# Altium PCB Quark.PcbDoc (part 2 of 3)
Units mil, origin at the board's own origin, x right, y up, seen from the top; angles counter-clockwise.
Board outline 1220.47 x 944.88 mil, 6 copper layers (Top1, Signal2, Gnd3, Power4, Signal5, Bottom6), stack 32.534 mil thick; 106 components, 182 nets, 776 pads, 404 vias.
Unrouted connection lines stored in the file: 82.
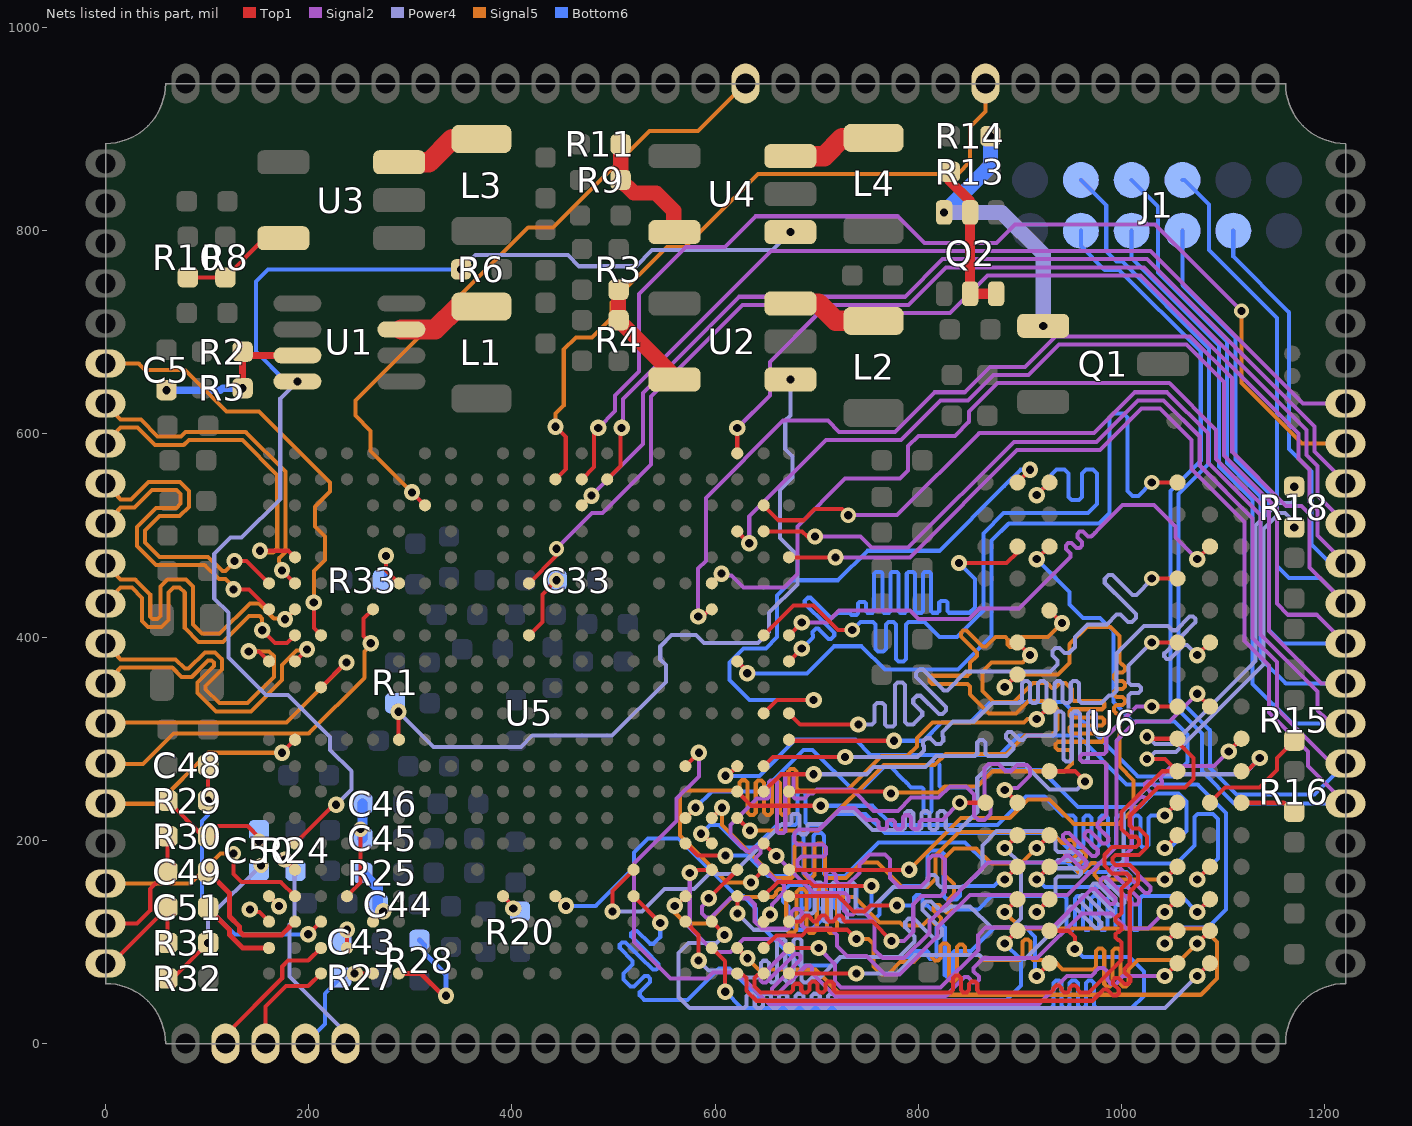
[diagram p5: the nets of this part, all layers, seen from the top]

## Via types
v1: diameter 16, hole 8, Top1 to Bottom6, tented both sides, 238 vias
v2: diameter 15, hole 8, Top1 to Bottom6, tented both sides, 166 vias

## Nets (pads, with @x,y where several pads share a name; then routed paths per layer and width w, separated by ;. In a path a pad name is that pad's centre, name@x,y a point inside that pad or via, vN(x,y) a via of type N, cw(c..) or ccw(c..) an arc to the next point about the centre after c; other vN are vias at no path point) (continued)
GPIOL8/PWR-STB: R6.1 U1.8 U4.1 U5.T2 | length 1265.3
  Top1 w4: U5.T2@186.46,197 224.46,235 v1(227,235)
  Power4 w4: v2(188.82,651.61) 172,634.8 172,536 134,498 123,498 107,482 107,438 121,424 121,380 158,343 179.56,343 221,301.56 221,289 242,268 242,250 v1(227,235) ; v2(350,762) 364,776 455,776 466,765 522,765 538,781 656.46,781 v2(674.06,798.6)
  Bottom6 w4: v2(188.82,651.61) 177.39,651.61 148,681 148,750 160,762 v2(350,762)
GPIOL9/PWR-DRAM: R1.1 U2.1 U5.M6 | length 765.6
  Top1 w4: v1(288.32,326.5) 288.32,299.5 U5.M6@288.82,299
  Power4 w4: v1(288.32,326.5) 322.82,292 409,292 420,303 498.49,303 551.49,356 551.49,372.51 546,378 546,391 557,402 581,402 589,394 642,394 653,405 653,424 681,452 681,480.35 664,497.35 664,545 676,557 676,578 669,585 669,613 674.06,618.06 v2(674.06,653.6)
GPIOL10/PWR-LED: pad.19 U5.V2 | length 227.8
  Top1 w4: v2(126,187) 126,167 134,159 172.46,159 U5.V2@186.46,145
  Signal5 w4: pad.19@0,157.48 83.48,157.48 113,187 v2(126,187)
HCEC: pad.16 U5.G5 | length 366.2
  Top1 w4: v1(261,394) 254,401 254,418.13 U5.G5@263.23,427.36
  Signal5 w4: pad.16@0.59,275 37,275 67,305 200,305 255,360 255,385.66 261,391.66 v1(261,394)
HHPD: pad.17 U5.M2 | length 212.3
  Top1 w4: v1(173.66,286.2) U5.M2@186.46,299
  Signal5 w4: pad.17@0.22,236 51,236 101.2,286.2 v1(173.66,286.2)
HSCL: pad.6 U5.H3 | length 437.2
  Top1 w4: v1(205,434) 205,408.82 U5.H3@212.05,401.77
  Signal5 w4: pad.6@0,669.29 32.71,669.29 ; 33,669 39,663 78,663 119,622 151,622 221,552 221,543.31 206,528.31 206,509 216,499 216,476 205,465 v1(205,434)
HSDA: pad.15 U5.K3 | length 295.8
  Top1 w4: U5.K3@212.05,350.59 236.46,375 v1(237.15,375)
  Signal5 w4: pad.15@1.04,316 178.15,316 v1(237.15,375)
HTX0_N: pad.9 U5.F1 | length 327.8
  Top1 w4: v1(127,475) 138.82,475 U5.F1@160.87,452.95
  Signal5 w4: pad.9@0,551.18 0,550.71 12.54,538.18 12.54,537.84 14.88,535.5 25.18,535.5 42.51,552.83 73.17,552.83 82,544 82,528 73,519 53,519 39,505 39,493 53,479 100.97,479 114.97,465 118.28,465 127,473.72 v1(127,475)
HTX0_P: pad.10 U5.G1 | length 327.4
  Top1 w4: v1(126,447) 141.23,447 U5.G1@160.87,427.36
  Signal5 w4: pad.10@0,511.81 0,512.28 12.54,524.82 12.54,525.15 14.88,527.5 28.5,527.5 45.83,544.83 69.86,544.83 74,540.69 74,531.31 69.69,527 49.69,527 31,508.31 31,489.69 49.69,471 97.66,471 111.66,457 118.28,457 126,449.28 v1(126,447)
HTX1_N: pad.11 U5.G2 | length 326.3
  Top1 w4: v1@173.66,414.57 v1(176.66,417.57) U5.G2@186.46,427.36
  Signal5 w4: pad.11@0,472.44 0,471.64 14.88,456.76 29.24,456.76 44,442 44,420.34 46.34,418 51,418 54,421 54,450 60.76,456.76 79.24,456.76 86,450 86,412.4 95.01,403.39 112.39,403.39 142,433 150.88,433 165.59,418.29 175.93,418.29 v1(176.66,417.57)
HTX1_P: pad.12 U5.H2 | length 328.6
  Top1 w4: v1(154.23,406.77) 167,394 178.69,394 U5.H2@186.46,401.77
  Signal5 w4: pad.12@0,433.07 0,433.88 14.88,448.76 25.93,448.76 36,438.69 36,416 42,410 55,410 62,417 62,444 66.76,448.76 72.93,448.76 78,443.69 78,409.09 91.7,395.39 115.7,395.39 141.09,420.77 151.8,420.77 154.14,418.43 154.14,406.86 v1(154.23,406.77)
HTX2_N: pad.14 U5.J2 | length 328.8
  Top1 w4: U5.J2@186.46,376.18 v1(198.25,387.98) v1@199.25,388.98
  Signal5 w4: pad.14@0,354.33 0,354.8 12.54,367.34 12.54,367.67 14.88,370.02 18.19,370.02 ; 18.21,370 65.69,370 74.78,360.91 84.88,360.91 101.03,377.06 104.5,377.06 106.68,374.87 106.68,371.4 98,362.72 90.54,355.25 90.54,345.15 98,337.69 108.69,327 143,327 173.63,357.63 173.63,372.63 187.9,386.9 197.18,386.9 v1(198.25,387.98)
HTX2_P: pad.13 U5.J1 | length 325.7
  Top1 w4: v1(141,386) 151.05,386 U5.J1@160.87,376.18
  Signal5 w4: pad.13@0,393.7 0,393.23 12.54,380.7 12.54,380.36 14.88,378.02 68.98,378.02 78.09,368.91 81.57,368.91 97.71,385.06 107.82,385.06 114.68,378.19 114.68,368.09 98.54,351.94 98.54,348.46 112,335 139.69,335 165.63,360.94 165.63,381.37 161.03,385.97 v1(141,386)
HTXC_N: pad.8 U5.E2 | length 328.3
  Top1 w4: v1(152,485) 180,485 U5.E2@186.46,478.54
  Signal5 w4: pad.8@0,590.55 0,591.36 14.88,606.24 31.45,606.24 48.69,589 77,589 82,594 134.69,594 169,559.69 169,487.2 165.09,483.29 153.71,483.29 v1(152,485)
HTXC_P: pad.7 U5.F2 | length 327.9
  Top1 w4: v1(173.66,465.75) U5.F2@186.46,452.95
  Signal5 w4: pad.7@0,629.92 0,629.12 14.88,614.24 34.76,614.24 51.34,597.66 74.34,597.66 78.69,602 138,602 177,563 177,483.89 173.09,479.98 170.75,477.64 170.75,474.32 171.36,473.71 171.36,468.04 v1(173.66,465.75)
I2C0_SCL: pad.61 U5.F11 | length 1115.7
  Top1 w4: U5.F11@416.77,452.95 444,480.18 v2(444,487) v2@444,491
  Signal2 w4: v2(444,487) 479,522 489,522 537,570 537,637 627,727 790.31,727 827.31,764 1021.94,764 1182,603.94 1182,579.31 1193,568.31 1193,539.28 pad.61@1220.47,511.81
I2C0_SDA: pad.62 U5.C13 | length 992.3
  Top1 w4: U5.C13@468.77,529.72 v1(478.27,539.22) v1@481.27,542.22
  Signal2 w4: v1(478.27,539.22) 529,589.95 529,640.31 623.69,735 787,735 824,772 1025.25,772 1190,607.25 1190,582.63 1220.47,552.15 pad.62@1220.47,551.18
I2C1_SCL: pad.63 U5.B13 | length 1082.4
  Top1 w4: U5.B13@468.77,555.32 481,567.54 481,601 v1@486,606
  Signal2 w4: v1(485,606) 501.4,622.4 501.4,637.71 525,661.31 525,737.69 571.31,784 609.63,784 639.85,814.22 779.78,814.22 806,788 877,788 895,806 1033,806 v2(1118,721)
  Signal5 w4: v2(1118,721) 1118,650 1177.45,590.55 pad.63@1220.47,590.55
I2C1_SDA: pad.64 U5.B14 | length 919.1
  Top1 w4: U5.B14@493.77,555.32 507,568.54 507,605 v1(508,606)
  Signal2 w4: v1(508,606) 509.4,607.4 509.4,634.4 655,780 1028.57,780 1178.65,629.92 pad.64@1220.47,629.92
I2C2_SCL: pad.78 U5.B12 | length 708.1
  Top1 w4: U5.B12@442.77,555.32 453,565.54 453,597 v1(443,607)
  Signal5 w4: v1(443,607) 443,620 451,628 451,683 463,695 479,695 498,714 498,729.31 552.69,784 570.37,784 606.37,820 640.87,854.5 642.37,856 721.15,856 745.63,856 768.31,856 839,856 851,868 851,902 866.14,917.14 pad.78@866.14,944.88
I2C2_SDA: pad.84 U5.C7 | length 644.7
  Top1 w4: v1(301.61,542.52) U5.C7@314.41,529.72
  Signal5 w4: v1(301.61,542.52) 261,583.13 261,603 246,618 246,632.94 416.06,803 440.25,803 535.25,898 583.04,898 pad.84@629.92,944.88
IR-RX: pad.26 R24.1 U5.U2 | length 216.9
  Top1 w4: v1@173.96,183.5 v1(176.36,181.1) U5.U2@186.46,171
  Power4 w4: v1(176.36,181.1) 186,171.46 186,122 181,117 181,66 pad.26@236.22,10.78
KEYADC: pad.25 R27.2 U5.AA5 | length 97.6
  Top1 w4: v1(245.23,69) U5.AA5@263.23,69
  Bottom6 w4: pad.25@196.85,0 216,19.15 216,49 R27.2@232,65
LINEINL: U5.V1 | length 18.1
  Top1 w4: U5.V1@160.87,145 v1@173.66,132.2
  other v1: 170.66,135.2
LINEINR: U5.W1 | length 23.7
  Top1 w4: v1(142.07,131.8) 144.37,129.5 151.37,129.5 U5.W1@160.87,120
LINEOUTL: pad.24 U5.AA3 | length 104.5
  Top1 w4: pad.24@157.48,0 157.48,36.48 177.5,56.5 199.55,56.5 U5.AA3@212.05,69
LINEOUTR: pad.23 U5.Y3 | length 143.2
  Top1 w4: pad.23@118.11,1.42 118.11,8.42 173.96,64.27 173.96,75.96 179.5,81.5 199.55,81.5 U5.Y3@212.05,94
MBIAS: C48.1 R29.2 U5.W3 | length 272.2
  Top1 w4: v2(101,239) C48.1@101,274 ; v1(199.55,107.5) U5.W3@212.05,120
  Bottom6 w4: v2(101,239) 101,225 95,219 95,140 127.5,107.5 v1(199.55,107.5)
MIC1N: C51.2 pad.21 R31.2 | length 118.9
  Top1 w4: pad.21@0,78.74 5.74,78.74 C51.2@61,134 R31.2@61,99
MIC1P: C49.2 pad.20 R30.1 | length 129.3
  Top1 w4: pad.20@0,118.11 31,118.11 44,131.11 44,152 C49.2@61,169 R30.1@61,204
MICIN1N: C51.1 U5.Y1 | length 79.9
  Top1 w5: C51.1@101,134 101,133 122,112 122,107 135,94 U5.Y1@160.87,94
MICIN1P: C49.1 U5.W2 | length 132.8
  Top1 w5: C49.1@101,169 122,148 122,125 132,115 132,110.27 135.27,107 173.46,107 U5.W2@186.46,120
NetC5_1: C5.1 R2.1 R5.2 U1.7 | length 161.9
  Top1 w7: v2(135,645) R2.1@135,681 ; R2.1@138.8,677.2 U1.7@188.82,677.2
  Bottom6 w7: v2(60,643) 113,643 115,645 v2(135,645)
NetC33_1: C33.1 U5.H11 | length 65.5
  Top1 w4: U5.H11@416.77,401.77 430,415 430,442 v2(444,456)
NetC43_1: C43.1 U5.Y4 | length 18
  Top1 w4: U5.Y4@237.64,94 v1(237.64,112)
NetC44_2: C44.2 R25.2 U5.W5 | length 57.9
  Top1 w4: U5.W5@263.23,120 v1(273.33,130.1) v1@275.73,132.5
  Bottom6 w10: R25.2@253,168 268,153 C44.2@268,134
NetC45_2: C45.2 C46.2 U5.V4 | length 105.5
  Top1 w4: U5.V4@237.64,145 251,158.36 v2(251,211)
  Bottom6 w10: C45.2@253,202 C46.2@253,236
NetC50_1: C50.1 R31.1 R32.2 | length 152.4
  Top1 w4: R32.2@61,64 66,64 v2(101,99)
  Power4 w4: v2(101,99) 101,123.32 v2(153,175.31)
NetC50_2: C50.2 R29.1 R30.2 | length 113.2
  Top1 w4: R29.1@61,239 96,204 R30.2@101,204 101.34,204 111.34,214 140,214 v2@151,203
  other v2: 151,199
NetL1_1: L1.1 U1.3 | length 88.1
  Top1 w20: U1.3@291.18,702.8 324.49,702.8 346.97,725.28 L1.1@370,725.28
NetL2_1: L2.1 U2.3 | length 89
  Top1 w20: U2.3@674.06,728.4 701.6,728.4 718.72,711.28 L2.1@756,711.28
NetL3_1: L3.1 U3.3 | length 90.4
  Top1 w20: U3.3@289.06,867.4 318.4,867.4 341.28,890.28 L3.1@370,890.28
NetL4_1: L4.1 U4.3 | length 89.3
  Top1 w20: U4.3@674.06,873.4 707.4,873.4 725.28,891.28 L4.1@756,891.28
NetQ1_1: Q1.1 Q2.3 R14.1 | length 279
  Power4 w15: v2(825.41,818) 882,818 922.94,777.06 v2(922.94,706.4)
  Bottom6 w15: v2(825.41,818) 871,863.59 v2(871,893)
NetQ2_2: Q2.2 Q2.5 Q2.6 R13.2 | length 153.9
  Top1 w10: R13.2@831,858 831,849 851,829 Q2.2@851,818 Q2.5@851,738 Q2.6@876.59,738
NetR3_2: R3.2 R4.2 U2.5 | length 111.2
  Top1 w10: U2.5@560.06,653.6 U2.5@560.06,656.94
  Top1 w15: R3.2@505,742 R4.2@505,712 U2.5@560.06,656.94
NetR8_2: R8.2 R10.2 U3.5 | length 110
  Top1 w4: R10.2@81,754 R8.2@118,754 156.6,792.6 U3.5@175.06,792.6
NetR9_1: R9.1 R11.2 U4.5 | length 121.8
  Top1 w10: U4.5@559.19,798.6 U4.5@560.06,798.6
  Top1 w15: R11.2@507,885 R9.1@507,850 520,837 542,837 559.19,819.81 U4.5@559.19,798.6
NetR15_1: R15.1 U6.L8 | length 115.3
  Top1 w4: U6.L8@1087,237 1102,252 1136,252 1153,269 1153,281 R15.1@1170,298
NetR16_1: R16.1 U6.L9 | length 55.7
  Top1 w4: U6.L9@1118,237 1159.66,237 1168.66,228 R16.1@1170,228
NetR20_1: R20.1 U5.V10 | length 17.7
  Top1 w4: U5.V10@391.18,145 v1@403.68,132.5
  other v1: 401.28,132.9
NetR28_2: R28.2 U5.AA6 | length 121.1
  Top1 w5: U5.AA6@288.82,69 310.38,69 332.38,47 v1(335,47)
  Bottom6 w5: R28.2@309,102 313.84,97.16 313.84,89.16 335,68 v1(335,47)
NetR33_2: R33.2 U5.F6 | length 65.6
  Top1 w4: v1@276,484 276,465.77 U5.F6@288.82,452.95
  Bottom6 w4: R33.2@273,456 276,459 v1@276,484
  other v1: 276,480
SA0: U5.T17 U6.N3 | length 757
  Top1 w4: U5.T17@570.77,197 582.89,184.89 v1(610.11,184.89) ; v1(916.51,161.5) U6.N3@929.01,174
  Bottom6 w4: v1(610.11,184.89) 632.11,184.89 652,165 674.5,165 677,167.5 677,204.5 679.5,207 684.5,207 687,204.5 687,167.5 689.5,165 694.5,165 697,167.5 697,204.5 699.5,207 704.5,207 707,204.5 707,167.5 709.5,165 728,165 761,198 846,198 866,178 947,178 956,169 1005,169 1009,165 1009,158 1005,154 924.85,154 917.35,161.5 v1(916.51,161.5)
SA1: U5.U18 U6.P7 | length 831.6
  Top1 w4: v1(575,168) 577.3,170.3 582.64,170.3 583.34,171 U5.U18@596.77,171 ; v1(1042.5,129.5) U6.P7@1055,142
  Signal2 w4: v1(575,168) 575,114 599,90 615,90 628,103 662,103 670.29,94.71 670.29,91.32 644.6,65.63 644.6,62.23 646.86,59.97 650.25,59.97 677.64,87.36 678.53,88.25 681.92,88.25 684.19,85.98 684.19,82.59 655.91,54.31 655.91,50.92 658.17,48.66 661.57,48.66 688.96,76.04 689.84,76.93 693.24,76.93 695.5,74.67 695.5,71.28 695.5,69.5 718,47 827,47 837.5,57.5 841.36,61.36 845.32,65.32 848.71,65.32 853.87,60.16 857.26,60.16 859.52,62.42 859.52,65.82 854.37,70.97 854.37,74.37 855.5,75.5 864,84 917,84 961,128 989.97,128 1004.97,113 1026,113 v1(1042.5,129.5)
SA2: U5.V19 U6.P3 | length 793.4
  Top1 w4: U5.V19@621.77,145 622,144.77 v1(622,128) ; v1(916.51,129.5) U6.P3@929.01,142
  Power4 w4: v1(622,128) 638,112 670,112 677.5,119.5 680.33,122.33 685.99,127.99 ; 686,128 690,128 695.6,128 698,130.4 698,156.18 700.4,158.58 703.6,158.58 706,156.18 706,128 706,122.6 708.4,120.2 711.6,120.2 714,122.6 714,128 714,156.18 716.4,158.58 719.6,158.58 722,156.18 722,128 722,122.6 724.4,120.2 727.6,120.2 730,122.6 730,128 730,156.18 732.4,158.58 735.6,158.58 738,156.18 738,130.4 740.4,128 746,128 749,128 750.5,129.5 775,154 804,154 806,154 809,157 809,163 812,166 816,166 819,163 819,157 822,154 828,154 845,154 863,172 863,195 877,209 926,209 935,200 935,192.5 935,190.9 937.4,188.5 957.6,188.5 960,186.1 960,182.9 957.6,180.5 937.4,180.5 935,178.1 935,174.9 937.4,172.5 957.6,172.5 960,170.1 960,166.9 957.6,164.5 937.4,164.5 935,162.1 935,161 935,147.99 v1(916.51,129.5)
SA3: U5.V20 U6.N2 | length 758.1
  Top1 w4: U5.V20@647.77,145 661.77,159 693,159 697,155 v1(754,155) v1@750,159 ; v1(885.01,161.5) U6.N2@897.51,174
  Bottom6 w4: v1(754,155) 754,137 749,132 741,132 739,134 739,153 736,156 735,156 733,156 726.6,156 725,154.4 725,134.6 723.4,133 718.6,133 717,134.6 717,154.4 715.4,156 710.6,156 709,154.4 709,134.6 707.4,133 702.6,133 701,134.6 701,154.4 699.4,156 694.6,156 693,154.4 693,134.6 691.4,133 686.6,133 685,134.6 685,154.4 683.4,156 677,156 673,156 667,150 667,140 672,135 672,120 680,112 695,112 704,121 756,121 762,127 762,140 777,155 801,155 ; 803.4,155 801,155 ; v1(885.01,161.5) 881.01,161.5 874.51,155 856,155 844.2,155 841,151.8 841,145.2 837.8,142 828.2,142 825,145.2 825,155 825,186.8 821.8,190 812.2,190 809,186.8 809,158.2 805.8,155 801,155
SA4: U5.V21 U6.P8 | length 757.8
  Top1 w4: U5.V21@672.77,145 721,145 736,130 747,130 753,136 v1(779,136) ; v1(1074.5,129.5) U6.P8@1087,142
  Bottom6 w4: v1(779,136) 792,136 793.6,136 796,138.4 796,143.6 798.4,146 801.6,146 804,143.6 804,138.4 806.4,136 809,136 813,132 859,132 872,145 934,145 938,145 943.6,145 946,142.6 946,114.4 948.4,112 951.6,112 954,114.4 954,142.6 956.4,145 959.6,145 962,142.6 962,114.4 964.4,112 967.6,112 970,114.4 970,142.6 972.4,145 975.6,145 978,142.6 978,114.4 980.4,112 983.6,112 986,114.4 986,142.6 988.4,145 991.6,145 994,142.6 994,114.4 996.4,112 999.6,112 1002,114.4 1002,142.6 1004.4,145 1007.6,145 1010,142.6 1010,114.4 1012.4,112 1015.6,112 1018,114.4 1018,142.6 1020.4,145 1023,145 1059,145 v1(1074.5,129.5)
SA5: U5.Y19 U6.P2 | length 776.2
  Top1 w4: U5.Y19@621.77,94 v1(631.87,83.9) v1@634.27,81.5 ; v1(885.01,129.5) U6.P2@897.51,142
  Signal5 w4: v1(631.87,83.9) 642.77,73 698.63,73 723.63,48 1078,48 1094,64 1094,100 1081,113 901.51,113 v1(885.01,129.5)
SA6: U5.Y20 U6.R8 | length 776.2
  Top1 w4: U5.Y20@647.77,94 660.27,106.5 685.5,106.5 691,112 730,112 v1(739,103) ; v1(1074.5,98.5) U6.R8@1087,111
  Signal5 w4: v1@739,98 v1(739,103) 751,103 756,98 756,76 764,68 770,68 782.5,80.5 795.5,80.5 802,87 811.6,87 814,84.6 814,84.28 816.4,81.88 819.6,81.88 822,84.28 822,95.83 824.4,98.23 827.6,98.23 830,95.83 830,63.82 832.4,61.42 835.6,61.42 838,63.82 838,95.1 840.4,97.5 843.6,97.5 846,95.1 846,89.4 848.4,87 859,87 864,82 900.1,82 902.5,84.4 902.5,100.18 904.9,102.58 908.1,102.58 910.5,100.18 910.5,84.4 912.9,82 933,82 942,73 972.6,73 975,75.4 975,91.18 977.4,93.58 980.6,93.58 983,91.18 983,58.4 985.4,56 988.6,56 991,58.4 991,91.18 993.4,93.58 996.6,93.58 999,91.18 999,58.4 1001.4,56 1004.6,56 1007,58.4 1007,73 1016,82 1058,82 v1(1074.5,98.5)
SA7: U5.V15 U6.R2 | length 756.9
  Top1 w4: U5.V15@519.77,145 v1@546,118.77 ; v1(885.01,98.5) U6.R2@897.51,111
  Bottom6 w4: v1(546,118.76) 546,105 543.17,102.17 539.21,98.21 535.82,98.21 523.13,110.9 519.73,110.9 517.47,108.64 517.47,105.25 531.86,90.86 544.3,78.41 544.3,75.02 542.04,72.76 538.65,72.76 526.2,85.2 511.81,99.59 508.42,99.59 506.16,97.33 506.16,93.93 518.85,81.24 518.85,77.85 514.89,73.89 510,69 510,63 512.83,60.17 516.79,56.21 520.18,56.21 530.38,66.41 533.78,66.41 536.04,64.15 536.04,60.75 525.84,50.56 525.84,47.16 529.8,43.2 530,43 534,43 537,43 573,43 604,74 614,74 636.15,51.85 638.41,49.58 645,43 887,43 901,57 901,82.51 v1(885.01,98.5)
SA8: U5.W18 U6.T8 | length 794
  Top1 w4: U5.W18@596.77,120 609.27,107.5 v1(609.27,106.96) ; v1(1074.5,66.5) U6.T8@1087,79
  Power4 w4: v1(609.27,106.96) 601.32,99 574,99 564,89 564,46 575,35 627,35 628.6,35 631,37.4 631,46.6 633.4,49 636.6,49 639,46.6 639,37.4 641.4,35 644.6,35 647,37.4 647,46.6 649.4,49 652.6,49 655,46.6 655,37.4 657.4,35 660.6,35 663,37.4 663,46.6 665.4,49 668.6,49 671,46.6 671,37.4 673.4,35 676.6,35 679,37.4 679,46.6 681.4,49 684.6,49 687,46.6 687,37.4 689.4,35 692.6,35 695,37.4 695,46.6 697.4,49 700.6,49 703,46.6 703,37.4 705.4,35 708.6,35 711,37.4 711,46.6 713.4,49 716.6,49 719,46.6 719,37.4 721.4,35 723,35 1043,35 v1(1074.5,66.5)
SA9: U5.Y18 U6.R3 | length 757.8
  Top1 w4: U5.Y18@596.77,94 609.77,81 609.77,51.23 v1(610,51) ; U6.R3@929.01,111 948,111 954,105 v1(954,93)
  Bottom6 w4: v1(610,51) 626,35 929,35 930.6,35 933,37.4 933,59.6 935.4,62 938.6,62 941,59.6 941,37.4 943.4,35 946.6,35 949,37.4 949,59.6 951.4,62 954.6,62 957,59.6 957,37.4 959.4,35 962.6,35 965,37.4 965,59.6 967.4,62 970.6,62 973,59.6 973,37.4 975.4,35 981,35 982,35 1010,35 1022,47 1022,71 1008,85 962,85 v1(954,93)
SA10: U5.P19 U6.L7 | length 757.4
  Top1 w4: U5.P19@621.77,248 635.77,234 v1(704,234) ; v1(1042.5,224.5) U6.L7@1055,237
  Bottom6 w4: v1(704,234) 755,234 774,215 878,215 906,243 924,243 942.5,224.5 946.5,224.5 952.1,224.5 954.5,222.1 954.5,195.81 956.9,193.41 960.1,193.41 962.5,195.81 962.5,222.1 964.9,224.5 968.1,224.5 970.5,222.1 970.5,195.4 972.9,193 976.1,193 978.5,195.4 978.5,222.1 980.9,224.5 984.1,224.5 986.5,222.1 986.5,195.4 988.9,193 992.1,193 994.5,195.4 994.5,222.1 996.9,224.5 1000.1,224.5 1002.5,222.1 1002.5,195.4 1004.9,193 1008.1,193 1010.5,195.4 1010.5,222.1 1012.9,224.5 1016.1,224.5 1018.5,222.1 1018.5,195.4 1020.9,193 1024.1,193 1026.5,195.4 1026.5,222.1 1028.9,224.5 1030,224.5 v1(1042.5,224.5)
SA11: U5.N19 U6.R7 | length 757.7
  Top1 w4: v1@609.27,260.5 U5.N19@621.77,273 ; v1(1042.5,98.5) U6.R7@1055,111
  Bottom6 w4: v1(610.27,263.5) 643.5,263.5 679,299 738,299 753,284 880,284 899,303 957,303 1005,255 1075,255 1103,227 1103,132 1085,114 1058,114 v1(1042.5,98.5)
SA12: U5.R18 U6.N7 | length 775.9
  Top1 w4: U5.R18@596.77,222 v1(606.87,232.1) v1@609.27,234.5 ; v1(1042.5,161.5) U6.N7@1055,174
  Signal5 w4: v1(606.87,232.1) 606.87,215.13 659,163 673,163 675,163 678,166 678,194 681,197 685,197 688,194 688,166 691,163 695,163 698,166 698,194 701,197 705,197 708,194 708,166 711,163 729,163 744,178 760,178 784,154 809,154 817,162 817,185 840,208 931,208 941.63,197.37 945.03,197.37 948,200.34 951.39,200.34 953.65,198.08 953.65,194.68 948.99,190.01 944.32,185.35 944.32,181.95 946.58,179.69 949.98,179.69 954.64,184.36 959.31,189.02 962.7,189.02 964.97,186.76 964.97,183.37 960.3,178.7 955.63,174.03 955.63,170.64 957.89,168.38 961.29,168.38 965.96,173.04 970.62,177.71 974.02,177.71 976.28,175.45 976.28,172.05 973.31,169.08 973.31,165.69 977.5,161.5 v1(1042.5,161.5)
SA13: U5.V12 U6.T3 | length 758.1
  Top1 w4: U5.V12@442.77,145 v1@455.27,132.5 ; v1(916.51,66.5) U6.T3@929.01,79
  Bottom6 w4: v1(453.27,135.5) 482.5,135.5 520,173 520,188 534,202 564,202 621,145 628,145 640,133 640,121 684,77 716,77 724,85 792,85 798,91 802,91 808.4,91 810,89.4 810,85 811.6,83.4 816.4,83.4 818,85 818,91 818,114.4 819.6,116 824.4,116 826,114.4 826,91 826,67.6 827.6,66 832.4,66 834,67.6 834,89.4 835.6,91 841,91 852,91 875,114 906,114 915,105 915,68.01 v1(916.51,66.5)
SA14: U5.N17 U6.T7 | length 831.6
  Top1 w4: U5.N17@570.77,273 v1(584,286.23) ; v1(1042.5,66.5) U6.T7@1055,79
  Signal2 w4: v1(584,286.23) 584,263 562,241 562,219 520,177 520,100 556,64 592,64 598,70 622,70 653,39 919,39 946.5,66.5 968,66.5 970.4,66.5 974,70.1 974,70.65 977.6,74.25 982.4,74.25 986,70.65 986,66.5 986,62.35 989.6,58.75 994.4,58.75 998,62.35 998,62.9 1001.6,66.5 1007,66.5 v1(1042.5,66.5)
SA15: U5.R17 U6.M7 | length 756.8
  Top1 w4: U5.R17@570.77,222 v1(580.87,232.1) v1@583.27,234.5 ; v1(1042.5,192.5) U6.M7@1055,205
  Bottom6 w4: v1(580.87,232.1) 596.77,248 646,248 687,289 696,289 736,249 743,249 766,272 773,272 785,260 787.83,257.17 793,252 797,252 803.4,252 805,250.4 805,228.6 806.6,227 811.4,227 813,228.6 813,252 813,274.4 814.6,276 819.4,276 821,274.4 821,253.6 822.6,252 828,252 856,252 873,269 921,269 957,233 1018,233 1031,246 1056,246 1064,238 1064,209 1047.5,192.5 v1(1042.5,192.5)
SBA0: U5.W17 U6.M2 | length 794
  Top1 w4: U5.W17@570.77,120 583.77,107 v1(583.77,81.54) ; v1(885.01,192.5) U6.M2@897.51,205
  Power4 w4: v1(583.77,81.54) 593.32,72 616,72 623,65 642.6,65 645,67.4 645,79.04 647.4,81.44 650.6,81.44 653,79.04 653,62.4 655.4,60 658.6,60 661,62.4 661,101.6 663.4,104 666.6,104 669,101.6 669,62.4 671.4,60 674.6,60 677,62.4 677,101.6 679.4,104 682.6,104 685,101.6 685,62.4 687.4,60 690.6,60 693,62.4 693,62.6 695.4,65 703,65 723,85 781,85 794.5,98.5 796.2,100.2 796.2,105.29 787.15,114.34 787.15,119.43 790.54,122.82 795.63,122.82 807.23,111.23 814.77,103.69 819.86,103.69 823.25,107.08 823.25,112.17 815.71,119.71 804.12,131.31 804.12,136.4 807.51,139.79 812.6,139.79 821.65,130.74 826.74,130.74 828.5,132.5 831,135 851,135 872,114 892,114 901,123 901,176.51 v1(885.01,192.5)
SBA1: U5.T18 U6.N8 | length 757.8
  Top1 w4: v1@584.27,209.5 U5.T18@596.77,197 ; v1(1074.5,161.5) U6.N8@1087,174
  Bottom6 w4: v1(586.27,206.5) 594.77,215 604,215 626,193 639,193 661,215 676,215 678.6,215 681,217.4 681,245.6 683.4,248 686.6,248 689,245.6 689,217.4 691.4,215 697,215 701,215 707,215 718,226 748,226 767,207 932,207 962,177 1054,177 1072,195 1072,223 1075,226 1090,226 1095,221 1095,182 v1(1074.5,161.5)
SBA2: U5.V17 U6.M3 | length 776
  Top1 w4: v1@558.27,132.5 U5.V17@570.77,145 ; v1(916.51,192.5) U6.M3@929.01,205
  Signal5 w4: v1(560.27,135.5) 560.27,128.73 571,118 591,118 617,144 655,144 657,144 660,147 660,149 663,152 667,152 670,149 670,144 670,112 673,109 677,109 680,112 680,144 680,149 683,152 687,152 690,149 690,144 690,112 693,109 697,109 700,112 700,144 700,149 703,152 707,152 710,149 710,144 710,112 713,109 717,109 720,112 720,141 723,144 727,144 737,144 762,119 782,119 785,116 804,116 809.5,121.5 812.9,121.5 816.58,117.83 819.97,117.83 822.23,120.09 822.23,123.48 816.86,128.86 814.97,130.75 814.97,134.14 817.23,136.4 820.63,136.4 822.51,134.51 827.89,129.14 831.28,129.14 833.55,131.4 833.55,134.8 829.87,138.47 829.87,141.87 835,147 835,157 825,167 825,181.69 835.31,192 857,192 872,177 901.01,177 v1(916.51,192.5)
SCAS: U5.U15 U6.K3 | length 794.4
  Top1 w4: v1(499,130) 499,150.23 U5.U15@519.77,171 ; U6.K3@929.01,268 954,268 v1(964,258)
  Power4 w4: v1(499,130) 528,130 550,152 579,152 594,167 617,167 666,216 673.4,216 675,217.6 675,224.4 676.6,226 681.4,226 683,224.4 683,207.6 684.6,206 689.4,206 691,207.6 691,214.4 692.6,216 708,216 721,229 736,229 755,210 783,210 784.6,210 787,212.4 787,226.62 789.4,229.02 792.6,229.02 795,226.62 795,212.4 797.4,210 800.6,210 803,212.4 803,226.62 805.4,229.02 808.6,229.02 811,226.62 811,212.4 813.4,210 816.6,210 819,212.4 819,226.62 821.4,229.02 824.6,229.02 827,226.62 827,212.4 829.4,210 830,210 840,210 858,228 858,261.31 871.69,275 904,275 929,250 956,250 v1(964,258)
SCK_N: R18.1 U5.AA20 U6.K7 | length 1161.3
  Top1 w4: U5.AA20@647.77,69 646.24,67.47 641.9,67.47 638.77,64.34 638.77,56.23 644.9,50.1 674.37,50.1 676.77,52.5 676.77,56.45 679.17,58.85 682.37,58.85 684.77,56.45 684.77,52.5 687.17,50.1 690.37,50.1 692.77,52.5 692.77,58.6 695.17,61 698.37,61 700.77,58.6 700.77,52.5 703.17,50.1 706.37,50.1 708.77,52.5 708.77,58.6 711.17,61 714.37,61 716.77,58.6 716.77,52.5 719.17,50.1 831.6,50.1 834,52.5 834,64.66 836.4,67.06 839.6,67.06 842,64.66 842,52.5 844.4,50.1 847.6,50.1 850,52.5 850,58.78 852.4,61.18 855.6,61.18 858,58.78 858,52.5 860.4,50.1 930.6,50.1 933,52.5 933,54.78 935.4,57.18 938.6,57.18 941,54.78 941,52.5 943.4,50.1 946.6,50.1 949,52.5 949,54.78 951.4,57.18 954.6,57.18 957,54.78 957,52.5 959.4,50.1 968.1,50.1 1000.1,82.1 1000.1,99.6 997.7,102 996.5,102 994.1,104.4 994.1,107.6 996.5,110 997.7,110 1000.1,112.4 1000.1,115.6 997.7,118 996.5,118 994.1,120.4 994.1,123.6 996.5,126 997.7,126 1000.1,128.4 1000.1,152.45 1008.24,160.59 1008.24,164.48 1005.18,167.54 990.84,167.54 983.1,175.28 983.1,185.79 990.84,193.54 1014.04,193.54 1017.1,196.59 1017.1,200.48 1014.04,203.54 1007.84,203.54 1000.1,211.28 1000.1,227.81 ; 1000,227.81 1040.19,268 U6.K7@1055,268 1043,280 v2(1025,280) v2@1025.25,279.75
  Signal2 w4: v2(1025,280) v2@1025.84,280
  Power4 w4: v2(1025,280) 1025.84,280 1032.84,287 1053.77,287 1139.89,373.12 1139.89,506.62 1155.27,522 1161,522 1170,513 v2(1170,508)
SCK_P: R18.2 U5.AA19 U6.J7 | length 1160.9
  Top1 w4: U5.AA19@621.77,69 623.3,67.47 627.65,67.47 630.77,64.34 630.77,51.91 640.59,42.1 971.41,42.1 982.45,53.13 985.84,53.13 991.64,47.33 995.03,47.33 997.29,49.6 997.29,52.99 991.5,58.79 991.5,62.18 993.76,64.45 997.15,64.45 1002.95,58.65 1006.35,58.65 1008.61,60.91 1008.61,64.3 1002.81,70.1 1002.81,73.5 1008.1,78.79 1008.1,149.14 1016.24,157.28 1016.24,167.79 1008.5,175.54 994.16,175.54 991.1,178.59 991.1,182.48 994.16,185.54 1017.36,185.54 1025.1,193.28 1025.1,203.79 1017.36,211.54 1011.16,211.54 1008.1,214.59 1008.1,224.1 1036.1,252.1 1062.4,252.1 1070.8,260.5 1070.8,281.2 1055,297 U6.J7@1055,300 1027,300 v2(1025,302)
  Signal2 w4: v2(1025,302) v2@1025.84,302
  Power4 w4: v2(1025,302) 1025.84,302 1032.84,295 1050.46,295 1131.89,376.43 1131.89,509.94 1153.95,532 1167.66,532 1170,534.34 v2(1170,548)
SCKE0: U5.AA21 U6.K9 | length 795.2
  Top1 w4: U5.AA21@672.77,69 v1(739,69) ; U6.K9@1118,268 1123.5,268 1136,280.5 v1(1136,281)
  Power4 w4: v1(739,69) 779,69 797,87 860,87 864,83 905,83 946.5,124.5 947.63,125.63 947.63,129.03 947.62,132.43 949.88,134.7 953.27,134.7 954.99,132.98 974.37,113.6 977.77,113.6 980.03,115.86 980.03,119.25 960.64,138.64 958.93,140.35 958.93,143.75 961.19,146.01 964.59,146.01 966.3,144.3 985.69,124.91 989.08,124.91 991.34,127.17 991.34,130.57 971.96,149.96 970.24,151.67 970.24,155.06 972.51,157.32 975.9,157.32 977.61,155.61 997,136.22 1000.4,136.22 1002.66,138.49 1002.66,141.88 984.97,159.57 984.97,162.97 986,164 1002,180 1002,229 1038,265 1120.5,265 1136,280.5 v1(1136,281)
SCKE1: U5.Y21 U6.J9 | length 832.2
  Top1 w4: U5.Y21@672.77,94 v1(702,94) ; v1(1105.5,287.5) U6.J9@1118,300
  Signal2 w4: v1(702,94) 718,78 718,61 724,55 822,55 859,92 859,107 866,114 932.31,114 970.45,152.13 973.84,152.13 988.47,137.5 991.87,137.5 994.13,139.76 994.13,143.16 979.5,157.79 979.5,161.18 981.76,163.44 985.15,163.45 1011.69,136.91 1015.08,136.91 1017.34,139.17 1017.34,142.57 993.81,166.1 990.81,169.1 990.81,172.5 993.07,174.76 996.47,174.76 1023,148.22 1026.4,148.22 1028.66,150.49 1028.66,153.88 1005.12,177.42 1005.12,186.81 1010,191.69 1010,234 1018.5,242.5 ; 1018.5,242.5 1021.9,242.5 1022.76,241.64 1026.16,241.64 1028.42,243.9 1028.42,247.3 1025.86,249.86 1023.3,252.42 1023.3,255.81 1025.56,258.08 1028.95,258.08 1031.51,255.51 1034.08,252.95 1037.47,252.95 1039.73,255.22 1039.73,258.61 1038.87,259.47 1038.87,262.87 1040,264 1049,273 1091,273 v1(1105.5,287.5)
SCS0: U5.W20 U6.L2 | length 760.7
  Top1 w4: U5.W20@647.77,120 647.77,120.39 654,126.61 v1(654,127) ; v1(885.01,249.5) U6.L2@897.51,237
  Signal2 w4: v1@655.9,128.9 655.9,136.9 668,149 668,156 664,160 660,160 641,179 640.18,179.82 640.18,183.21 644.63,187.66 644.63,191.05 642.37,193.32 638.97,193.32 634.53,188.87 631.13,188.87 630,190 615,205 615,215 641,241 651.4,241 653,242.6 653,257.4 654.6,259 659.4,259 661,257.4 661,208.6 662.6,207 667.4,207 669,208.6 669,263.69 670.6,265.29 675.4,265.29 677,263.69 677,242.6 678.6,241 688,241 693,246 696.2,246 700.2,250 735,250 756,229 780,229 793,242 820,242 831,253 847,253 855,245 855,224 859,220 865,220 871,226 871,239 865,245 865,271 869,275 879,275 886,268 891,268 897,274 907,274 910,271 910,264 897.66,251.66 887.17,251.66 v1(885.01,249.5)
SCS1: U5.W21 U6.L1 | length 831
  Top1 w4: U5.W21@672.77,120 682.37,120 683.97,120 686.37,122.4 686.37,123.62 688.77,126.02 691.97,126.02 694.37,123.62 694.37,122.4 696.77,120 699.97,120 702.37,122.4 702.37,123.62 704.77,126.02 707.97,126.02 710.37,123.62 710.37,122.4 712.77,120 715.97,120 718.37,122.4 718.37,123.62 720.77,126.02 723.97,126.02 726.37,123.62 726.37,121.63 728,120 754.67,120 v1(773.67,101) ; v2(840.75,237) U6.L1@866.02,237
  Signal2 w4: v1(773.67,101) 786,101 795,110 795,136.66 803.34,145 822,145 826,149 826,181 822,185 814,185 810,181 810,162 802,154 781,154 772,163 772,181 767,186 752,186 742,176 742,168 731,157 722,157 719,160 719,166 714.66,170.34 711.34,170.34 709,168 709,159 706,156 700,156 681,175 681,180 685,184 706.66,184 709,186.34 709,193 706,196 681,196 678,199 678,207 681.5,210.5 702.5,210.5 724,232 737,232 749,220 759,220 761,218 761,213 763,211 767,211 769,213 769,218 771,220 775,220 777,218 777,213 779,211 783,211 785,213 785,222.69 787,224.69 791,224.69 793,222.69 793,213 795,211 799,211 801,213 801,218 803,220 823.75,220 v2(840.75,237)
SDC0-CLK: J1.4 pad.55 U5.D20 | length 1716.6
  Top1 w4: U5.D20@647.77,504.13 685.66,504.13 690.79,499 v1(698.4,499)
  Signal2 w4: v1(698.4,499) 743,499 754,488 790,488 894,592 975.31,592 1016.31,633 1041.37,633 1077,597.37 1077,568.75 1129,516.75 1129,399.31 1153,375.31 1153,329.31 1206.72,275.59 pad.55@1220.47,275.59
  Bottom6 w4: J1.4@960,850 985,825 985,779.41 994.88,769.53 1000.78,769.53 1086,684.31 1086,570.69 1056,540.69 1056,339.31 1087,308.31 1087,271.31 1113.31,245 1189.88,245 pad.55@1220.47,275.59
SDC0-CMD: J1.6 pad.57 U5.F18 | length 1593.2
  Top1 w4: U5.F18@596.77,452.95 v1(606.27,462.45) v1@609.27,465.45
  Signal2 w4: v1(606.27,462.45) 608.03,460.69 616.31,460.69 628,449 668,449 681,462 681,509 728,556 781.84,556 790,564.16 790,588 800,598 836,598 850,612 850,622 878,650 1047,650 1093,604 1093,575.37 1145,523.37 1145,406 1196.67,354.33 pad.57@1220.47,354.33
  Bottom6 w4: J1.6@1010,850 1036.09,823.91 1036.09,758.91 1104,691 1104,571.31 1136.66,538.65 ; 1137,538.65 1137,379 1161.67,354.33 pad.57@1220.47,354.33
SDC0-D0: J1.9 pad.60 U5.A19 | length 1252.5
  Top1 w4: U5.A19@621.77,580.91 v1(621.77,605.77)
  Signal2 w4: v1(621.77,605.77) 654,638 654,671 702,719 831,719 868,756 1018.63,756 1174,600.63 1174,576 1185,565 1185,533 1193,525 1193,499.91 pad.60@1220.47,472.44
  Bottom6 w4: J1.9@1110,800 1110,774.73 1165,719.73 1165,585 1187,563 1187,491 1201.58,476.42 1216.49,476.42 pad.60@1220.47,472.44
SDC0-D1: J1.7 pad.58 U5.D19 | length 1429.7
  Top1 w4: U5.D19@621.77,504.13 v1(633.57,492.34) v1@634.57,491.34
  Signal2 w4: v1(633.57,492.34) 633.57,518.57 709,594 783,594 822,633 849,633 874,658 908.31,658 938.31,688 1064,688 1101,651 1101,578.69 1153,526.69 1153,433 1164,422 1192.17,422 pad.58@1220.47,393.7
  Bottom6 w4: J1.7@1060,800 1060,746.31 1112,694.31 1112,574.97 1145,541.97 1145,407 1158.3,393.7 pad.58@1220.47,393.7
SDC0-D2: J1.5 pad.56 U5.C20 | length 1470.4
  Top1 w4: U5.C20@647.77,529.72 662.5,515 687,515 698,526 725,526 v2(731,520)
  Signal2 w4: v2(731,520) 779,520 860,601 973,601 1013,641 1044.69,641 1085,600.69 1085,572.06 1137,520.06 1137,402.63 1193,346.63 1193,328 1201.53,319.47 1215.96,319.47 pad.56@1220.47,314.96
  Bottom6 w4: J1.5@1010,800 1010,773 1096,687 1096,568 1129,535 1129,354 1168.04,314.96 pad.56@1220.47,314.96
SDC0-D3: J1.3 pad.54 U5.E21 | length 1659.3
  Top1 w4: U5.E21@672.77,478.54 v1(718.54,478.54)
  Signal2 w4: v1(718.54,478.54) 791.86,478.54 897.31,584 978.63,584 1019.63,625 1038.06,625 1069,594.06 1069,565.43 1121,513.43 1121,396 1145,372 1145,326 1183.5,287.5 1183.5,273.19 pad.54@1220.47,236.22
  Bottom6 w4: J1.3@960,800 960,785 983.47,761.53 997.47,761.53 1078,681 1078,574 1048,544 1048,336 1079,305 1079,268 1110.78,236.22 pad.54@1220.47,236.22
SDC0-DET: J1.8 pad.59 U5.G18 | length 1525
  Top1 w4: v1(583.36,420.36) 585.66,422.66 589.9,422.66 594.61,427.36 U5.G18@596.77,427.36
  Signal2 w4: v1(583.36,420.36) 583.36,467.36 591,475 591,537 667,613 711,613 722,602 777,602 816,641 845.69,641 870.69,666 905,666 935,696 1067.31,696 1109,654.31 1109,582 1162,529 1177,529 1185,521 1185,468.54 pad.59@1220.47,433.07
  Bottom6 w4: J1.8@1060,850 1062,850 1086,826 1086,781 1153,714 1153,470 1165,458 1195.54,458 pad.59@1220.47,433.07
SDQ0: U5.N20 U6.F8 | length 794
  Top1 w4: U5.N20@647.77,273 656.77,282 v1(728,282) ; v1(1074.5,382.24) U6.F8@1087,394.74
  Power4 w4: v1(728,282) 799,282 804,287 805.41,288.41 805.41,292.66 804.71,293.36 804.71,297.61 807.54,300.44 811.78,300.44 814.61,297.61 817.44,294.78 821.68,294.78 824.51,297.61 824.51,301.85 823.8,302.56 823.8,306.8 828.5,311.5 834,317 855,317 873,335 898,335 899.6,335 902,337.4 902,354.6 904.4,357 907.6,357 910,354.6 910,337.4 912.4,335 915.6,335 918,337.4 918,354.6 920.4,357 923.6,357 926,354.6 926,337.4 928.4,335 931.6,335 934,337.4 934,354.6 936.4,357 939.6,357 942,354.6 942,337.4 944.4,335 947.6,335 950,337.4 950,354.6 952.4,357 955.6,357 958,354.6 958,337.4 960.4,335 966,335 974,335 980,335 982.83,337.83 987.5,342.5 990.5,342.5 995,347 995,384 1022,411 1045.74,411 1048.87,407.87 1050,406.74 1053.4,406.74 1066.97,420.32 1070.37,420.32 1072.63,418.05 1072.63,414.66 1057.36,399.38 1042.08,384.11 1042.08,380.72 1044.34,378.45 1047.74,378.45 1061.65,392.37 1064.37,392.37 v1(1074.5,382.24)
SDQ1: U5.P21 U6.F2 | length 776.6
  Top1 w4: U5.P21@672.77,248 771,248 v1(773,246) ; U6.F2@897.51,394.74 v1(910.01,382.24)
  Signal5 w4: v1(773,246) 774,247 820,247 826,253 858,253 873,268 944,268 951,275 951,286.6 948.6,289 937.29,289 934.89,291.4 934.89,294.6 937.29,297 980.6,297 983,299.4 983,302.6 980.6,305 951,305 948.93,307.07 948.93,310.93 951,313 980.6,313 983,315.4 983,318.6 980.6,321 951,321 949,323 949,327 951,329 980.6,329 983,331.4 983,334.6 980.6,337 953.4,337 951,339.4 951,349 945,355 939.4,355 937,352.6 937,352.27 934.6,349.87 931.4,349.87 929,352.27 929,352.6 926.6,355 913,355 894,336 874,336 863,347 863,366 872,375 902.77,375 v1(910.01,382.24)
SDQ2: U5.P20 U6.F7 | length 795
  Top1 w4: U5.P20@647.77,248 664.77,265 v1(697,265) ; v2(1029.73,394.74) U6.F7@1055,394.74
  Power4 w4: v1(697,265) 749,265 756,272 807,272 818,283 854,283 855.6,283 858,285.4 858,296.18 860.4,298.58 863.6,298.58 866,296.18 866,285.4 868.4,283 874,283 882,283 887,283 889.83,285.83 893.79,289.79 893.79,293.18 886.17,300.8 886.17,304.2 888.43,306.46 891.82,306.46 899.45,298.84 902.84,298.84 904,300 907,303 931,303 932.6,303 935,305.4 935,324.6 937.4,327 940.6,327 943,324.6 943,303 943,279.82 945.4,277.42 948.6,277.42 951,279.82 951,303 951,324.6 953.4,327 956.6,327 959,324.6 959,303 959,279.82 961.4,277.42 964.6,277.42 967,279.82 967,303 967,324.6 969.4,327 972.6,327 975,324.6 975,305.4 977.4,303 978,303 986,303 1007,324 1007,340 1007,342.6 1009.4,345 1016.6,345 1019,347.4 1019,350.6 1016.6,353 1009.4,353 1007,355.4 1007,357 1007,372.01 v2(1029.73,394.74)
SDQ3: U5.U21 U6.G2 | length 776.7
  Top1 w4: U5.U21@672.77,171 v1(791,171) ; v1(885.01,350.74) U6.G2@897.51,363.24
  Signal5 w4: v1(791,171) 842,222 890,222 908,240 929,240 953,216 997,216 1012,231 1012,259 998,273 998,322.6 995.6,325 994.82,325 992.42,327.4 992.42,330.6 994.82,333 1001.18,333 1003.58,335.4 1003.58,338.6 1001.18,341 994.82,341 992.42,343.4 992.42,346.6 994.82,349 1001.18,349 1003.58,351.4 1003.58,354.6 1001.18,357 994.82,357 992.42,359.4 992.42,362.6 994.82,365 1001.18,365 1003.58,367.4 1003.58,370.6 1001.18,373 1000.4,373 998,375.4 998,401 989,410 966,410 949,393 949,374.69 937.31,363 897.27,363 v1(885.01,350.74)
SDQ4: U5.R19 U6.E3 | length 775.7
  Top1 w4: U5.R19@621.77,222 v1(634.27,209.5) ; U6.E3@929.01,426.24 v1(941.51,413.74)
  Signal5 w4: v1(634.27,209.5) 701.5,209.5 766,274 816,274 827,285 887,285 905,303 930.82,303 937,309.18 937,329 929,337 908.25,337 896.25,325 869.75,325 851,343.75 851,351.6 848.6,354 813.4,354 811,356.4 811,359.6 813.4,362 848.6,362 851,364.4 851,375 857.63,381.63 857.63,385.03 841.93,400.72 841.93,404.12 844.2,406.38 847.59,406.38 863.29,390.68 866.68,390.68 876,400 885.6,400 888,397.6 888,392.64 890.4,390.24 893.6,390.24 896,392.64 896,397.6 898.4,400 927.77,400 v1(941.51,413.74)
SDQ5: U5.T20 U6.H7 | length 830.9
  Top1 w4: U5.T20@647.77,197 v1(660.27,184.5) ; v2(1029.73,331.75) U6.H7@1055,331.75
  Signal2 w4: v1(660.27,184.5) 660.27,184.41 696.69,148 728,148 731.23,144.77 731.23,139.68 727.13,135.58 727.13,130.49 730.52,127.1 735.61,127.1 739.71,131.2 744.8,131.2 746.5,129.5 757,119 757,92 765,84 786,84 811,109 811,120.31 868.69,178 938,178 944.79,184.79 948.18,184.79 959.63,173.34 963.03,173.34 965.29,175.6 965.29,178.99 952.14,192.14 942.58,201.71 942.58,205.1 944.84,207.36 948.23,207.36 970.95,184.65 974.34,184.65 976.6,186.91 976.6,190.31 963.46,203.46 963.46,206.47 966.1,209.11 969.11,209.11 981.34,196.88 984.74,196.88 987,199.14 987,202.54 976.47,213.07 976.47,216.47 985,225 985,274.6 982.6,277 961.49,277 959.09,279.4 959.09,282.6 961.49,285 982.6,285 985,287.4 985,302 1014.75,331.75 v2(1029.73,331.75)
SDQ6: U5.U19 U6.H8 | length 831.5
  Top1 w4: v1(593.77,143) U5.U19@621.77,171 ; v1(1074.5,344.25) U6.H8@1087,331.75
  Signal2 w4: v1(593.77,143) 593.77,141.43 587,134.66 587,128 591,124 596,124 615,143 633,143 639,137 639,120 646,113 670.29,113 672.29,113 675.29,116 675.29,129.36 678.29,132.36 682.29,132.36 685.29,129.36 685.29,116 688.29,113 695,113 714,113 720,107 720,96 730,86 749,86 767,68 781.31,68 819,105.69 819,114 851,146 947,146 995,194 995,298 1014,317 1047.25,317 v1(1074.5,344.25)
SDQ7: U5.U20 U6.H3 | length 775
  Top1 w4: v1(635.27,158.5) U5.U20@647.77,171 ; v1(916.51,319.25) U6.H3@929.01,331.75
  Signal5 w4: v1(635.27,158.5) 611.5,158.5 565.27,204.73 565.27,244.27 570,249 621.6,249 624,251.4 624,256.72 626.4,259.12 629.6,259.12 632,256.72 632,227.4 634.4,225 637.6,225 640,227.4 640,256.6 642.4,259 645.6,259 648,256.6 648,227.4 650.4,225 653.6,225 656,227.4 656,256.6 658.4,259 661.6,259 664,256.6 664,227.4 666.4,225 669.6,225 672,227.4 672,267.69 674.4,270.09 677.6,270.09 680,267.69 680,251.4 682.4,249 729.69,249 763.69,283 789,283 798.5,292.5 798.5,300.5 814,316 904,316 907.25,319.25 v1(916.51,319.25)
SDQ8: U5.J19 U6.A7 | length 757.8
  Top1 w4: U5.J19@621.77,376.18 v1@634.57,363.39 ; v2(1029.73,552.22) U6.A7@1055,552.22
  Bottom6 w4: v1(631.57,364.39) 690.39,364.39 717,391 744,391 767,368 839,368 872,401 872,495 889,512 978,512 988,522 988,616 992,620 1002,620 1006,616 1006,544 1011,539 1016.51,539 v2(1029.73,552.22)
SDQ9: U5.H20 U6.A3 | length 757.7
  Top1 w4: U5.H20@647.77,401.77 677,431 697,431 721,407 v2(735,407) ; v1(916.51,539.72) U6.A3@929.01,552.22
  Bottom6 w4: v2(735,407) 743,415 748,415 755.5,415 758,412.5 758,388.31 760.5,385.81 765.5,385.81 768,388.31 768,412.5 770.5,415 775.5,415 778,412.5 778,378.5 780.5,376 785.5,376 788,378.5 788,412.5 790.5,415 798,415 806,415 821,400 837.94,400 864,426.06 864,502 884,522 967,522 976,531 976,561 972,565 965,565 961,561 961,538 958,535 951,535 948,538 948,561 944,565 936,565 931,560 931,554.21 v1(916.51,539.72)
SDQ10: U5.H21 U6.C8 | length 542
  Top1 w4: U5.H21@672.77,401.77 v1(685.27,414.27) ; v1(1074.5,476.73) U6.C8@1087,489.23
  Signal2 w4: v1(685.27,414.27) 710.27,414.27 722,426 792,426 800,418 850,418 860,428 899,428 945,474 945.89,474.89 949.85,478.85 949.85,482.24 945.16,486.93 945.16,490.33 947.42,492.59 950.81,492.59 955.5,487.9 958.9,487.9 961.16,490.16 961.16,493.55 956.47,498.25 956.47,501.64 958.73,503.9 962.13,503.9 966.82,499.21 970.21,499.21 974.17,503.17 977,506 1001,530 1032,530 1053,509 1053,498.23 v1(1074.5,476.73)
SDQ11: U5.J21 U6.C2 | length 757.2
  Top1 w4: U5.J21@672.77,376.18 v1(685.27,388.68) ; v1(840,473) 887,473 897.51,483.51 U6.C2@897.51,489.23
  Bottom6 w4: v1(685.27,388.68) 694.8,398.2 696.49,399.9 696.49,402.16 695.83,402.82 695.83,405.09 699.23,408.48 701.49,408.48 703.28,406.69 711.61,398.36 713.87,398.36 717.27,401.76 717.27,404.02 708.94,412.35 688.19,433.1 688.19,435.36 691.58,438.75 693.84,438.75 713.46,419.14 715.73,419.14 720.25,423.66 720.59,424 724.59,424 732.11,424 732.59,423.52 734.19,421.92 738.99,421.92 740.59,423.52 740.59,424 740.59,433.04 742.19,434.64 746.99,434.64 748.59,433.04 748.59,425.6 750.19,424 754.99,424 756.59,425.6 756.59,462.4 758.19,464 762.99,464 764.59,462.4 764.59,425.6 766.19,424 770.99,424 772.59,425.6 772.59,462.4 774.19,464 778.99,464 780.59,462.4 780.59,425.6 782.19,424 786.99,424 788.59,425.6 788.59,462.4 790.19,464 794.99,464 796.59,462.4 796.59,425.6 798.19,424 802.99,424 804.59,425.6 804.59,462.4 806.19,464 810.99,464 812.59,462.4 812.59,425.6 814.19,424 818.99,424 820.59,425.6 820.59,433.89 822.19,435.49 826.99,435.49 828.59,433.89 828.59,425.6 830.19,424 836.59,424 844.59,424 850.63,424 856,429.37 856,433.37 856,441.37 856,449.37 856,457 853.17,459.83 847.51,465.49 841.86,471.14 841,472 v1(840,473)
SDQ12: U5.L20 U6.A2 | length 579.2
  Top1 w4: U5.L20@647.77,325 660.77,338 v1(697,338) ; U6.A2@897.51,552.22 v1(910.01,564.72)
  Bottom6 w4: v1(697,338) 634,338 614,358 614,375 628,389 650,389 661,400 661,441 676,456 721,456 750,485 821,485 885,549 900.72,564.72 v1(910.01,564.72)
SDQ13: U5.L21 U6.D7 | length 795.3
  Top1 w4: U5.L21@672.77,325 683.77,314 v1(741,314) ; v2(1029.73,457.73) U6.D7@1055,457.73
  Power4 w4: v1(741,314) 754.5,314 757,316.5 757,332.69 759.5,335.19 764.5,335.19 767,332.69 767,314 769.04,311.96 774.96,311.96 777,314 777,352.69 779.5,355.19 784.5,355.19 787,352.69 787,316.5 789.5,314 795,314 803.84,322.84 803.84,326.37 795,335.21 795,338.75 798.53,342.29 802.07,342.29 820.19,324.17 823.72,324.17 827.26,327.7 827.26,331.24 797.57,360.93 797.57,364.47 801.1,368 804.64,368 825.05,347.59 828.59,347.59 847,366 930,366 935.5,371.5 936.91,372.91 936.91,377.16 931.96,382.11 931.96,386.35 934.79,389.18 939.04,389.18 943.99,384.23 948.23,384.23 953.18,389.18 954,390 954,400 966.5,412.5 985.5,412.5 995.22,422.22 999.11,422.22 1006.57,414.77 1010.46,414.77 1014.35,418.66 1014.35,422.55 1004.95,431.95 983.5,453.39 983.5,457.28 987.39,461.17 991.27,461.17 1010.78,441.67 1014.67,441.67 1029.73,456.73 v2(1029.73,457.73)
SDQ14: U5.M21 U6.C3 | length 757.3
  Top1 w4: U5.M21@672.77,299 673.77,298 v1(776,298) ; v1(916.51,476.73) U6.C3@929.01,489.23
  Bottom6 w4: v1(776,298) 805,298 823,316 851,316 871,336 943,336 1016,263 1051,263 1065,277 1065,304 1052,317 1011,317 992,336 992,406 979,419 962,419 949,432 949,444.24 v1(916.51,476.73)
